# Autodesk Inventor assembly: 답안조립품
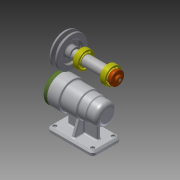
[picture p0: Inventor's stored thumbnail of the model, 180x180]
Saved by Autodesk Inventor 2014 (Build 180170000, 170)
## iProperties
Created: 2016-06
Part Number: 답안조립품
Document SubType Name: Assembly
Designer: user
Author: user
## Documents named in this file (11)
- C:\Users\user\Desktop\460608V1021\답안조립품.iam
- C:\Users\user\Desktop\460608V1021\본체.ipt
- C:\Users\user\Desktop\460608V1021\축.ipt
- C:\Users\user\Desktop\460608V1021\키 5 x 5 x 16.ipt
- C:\Users\user\Desktop\460608V1021\베어링 6004.ipt
- C:\Users\user\Desktop\460608V1021\커버.ipt
- C:\Users\user\Desktop\460608V1021\V벨트풀리.ipt
- C:\Users\user\Desktop\460608V1021\멈춤나사 M3x8.ipt
- C:\Users\user\Desktop\460608V1021\볼트 M4 x 12.ipt
- C:\Users\user\Desktop\460608V1021\어댑터슬리브.ipt
- C:\Users\user\Desktop\460608V1021\베어링 51202.ipt
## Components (6 placed, 2 different names)
1. V벨트풀리:1 — Mate:3, Insert:5, Mate:4
2. ISO 4762 M4 x 12:6 — Insert:9
3. ISO 4762 M4 x 12:1 — Insert:6
4. ISO 4762 M4 x 12:2
5. ISO 4762 M4 x 12:3
6. ISO 4762 M4 x 12:4
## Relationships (5: Insert 3, Mate 2)
- Mate:3: V벨트풀리:1
- Insert:5: V벨트풀리:1
- Mate:4: V벨트풀리:1
- Insert:6: ISO 4762 M4 x 12:1
- Insert:9: ISO 4762 M4 x 12:6
